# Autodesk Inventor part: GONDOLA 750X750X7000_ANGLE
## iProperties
Shininess: 64.0
Length Units: 11272
Angle Units: 11279
Time Units: 11290
Mass Units: 11286
Length Display Precision: 3
Angle Display Precision: 2
Compacted: True
Part Number: GONDOLA 750X750X7000_ANGLE
Document SubType Name: Modeling
Created: 2004-08
Designer: John Blackburn
Manufacturer: Standard
Standards Organization: Custom
Density: 0.0
Volumn: 0.0
Area: 0.0
PropertySet Name: Model Information
Control State: 0
Master: False
Checked Out: False
Author: John Blackburn
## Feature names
1. ExtrusionBlind1
